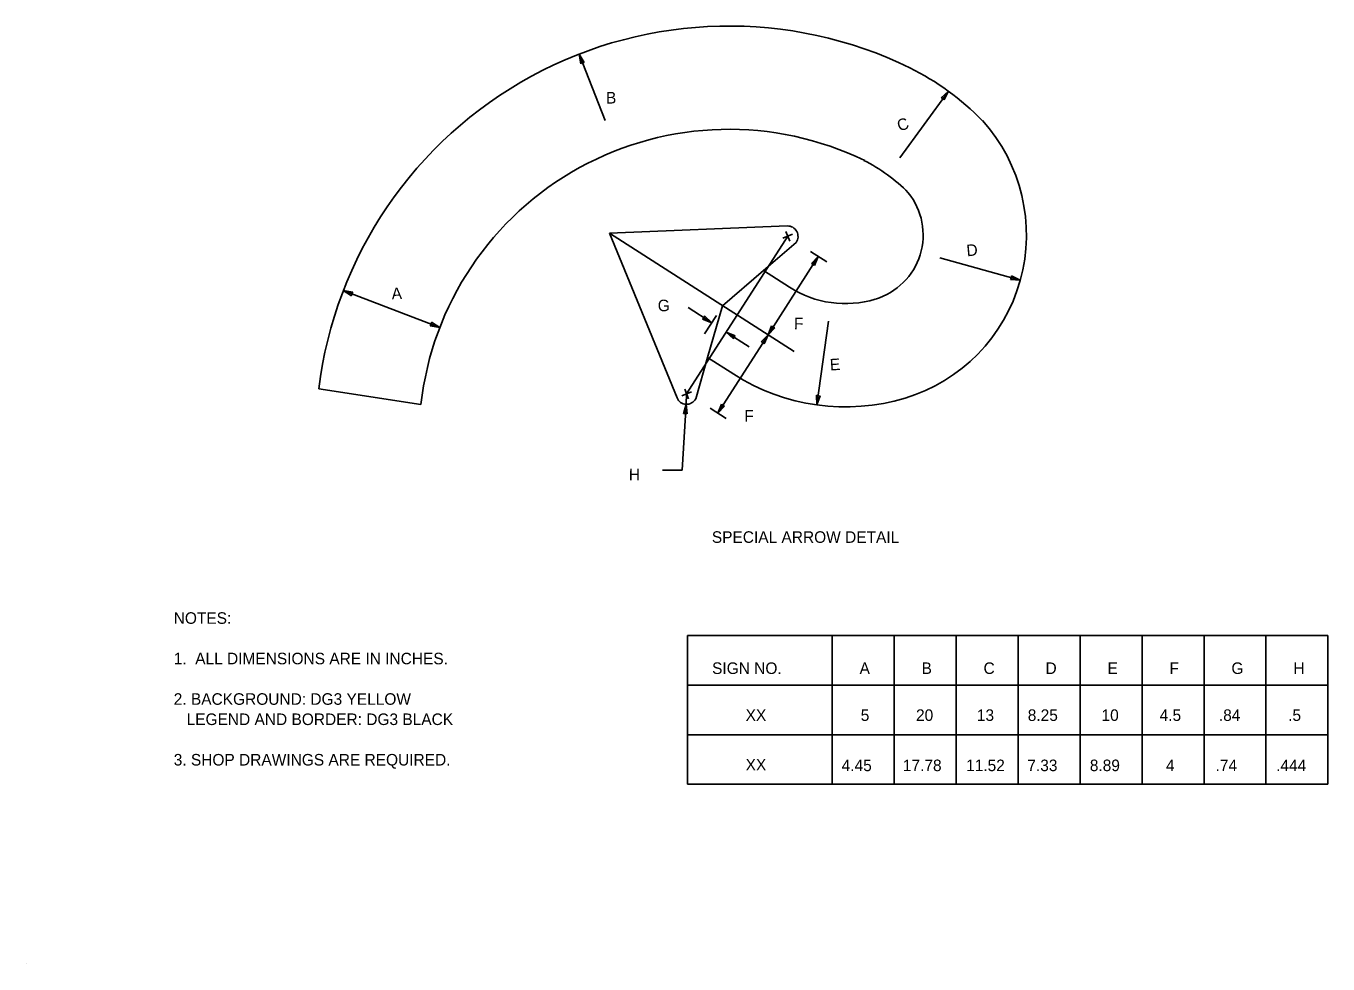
# Model space of a CAD drawing. Extents: x 582908 to 586040, y 1530940 to 1533040.
# Drawn here: x 582908 to 584484, y 1530940 to 1532075 of the extents above; entities that cross this region are included whole.
import ezdxf

# ---------------------------------------------------------------- set-up
doc = ezdxf.new("R2010")
doc.units = 0
for name, color, linetype in [('AdhocPoint_dp', 7, 'Continuous'), ('GSDims', 7, 'Continuous'), ('SignDetail', 7, 'Continuous'), ('TextLabel', 7, 'Continuous'), ('TextNotes', 7, 'Continuous'), ('TextTables', 7, 'Continuous')]:
    doc.layers.add(name, color=color, linetype=linetype)

msp = doc.modelspace()

# ---------------------------------------------------------------- linework, layer by layer
at = {"layer": 'AdhocPoint_dp'}
msp.add_line((582908.3, 1530939.8), (582908.3, 1530939.8), dxfattribs=at)
at = {"layer": 'GSDims'}
for p, q in [((583577.5, 1532040.8), (583609.1, 1531960.6)), ((583577.5, 1532040.8), (583579.7, 1532029.2)), ((583583.8, 1532030.8), (583577.5, 1532040.8)), ((583579.7, 1532029.2), (583581.4, 1532030.9)), ((583581.4, 1532030.9), (583583.8, 1532030.8)), ((583965.6, 1531915.4), (584024.4, 1531996.1)), ((584024.4, 1531996.1), (584015.8, 1531988)), ((584015.8, 1531988), (584018.1, 1531987.4)), ((584018.1, 1531987.4), (584019.3, 1531985.4)), ((584019.3, 1531985.4), (584024.4, 1531996.1)), ((583824.3, 1531818.1), (583835.9, 1531822.8)), ((583827.8, 1531826.2), (583832.4, 1531814.6)), ((583857.6, 1531801.8), (583877.2, 1531789.3)), ((583806.2, 1531701.1), (583866.9, 1531795.8)), ((583866.9, 1531795.8), (583858.8, 1531787.3)), ((583858.8, 1531787.3), (583861.1, 1531786.8)), ((583861.1, 1531786.8), (583862.5, 1531784.9)), ((583862.5, 1531784.9), (583866.9, 1531795.8)), ((584014.2, 1531794.2), (584111.4, 1531767.2)), ((584101, 1531770), (584099.6, 1531768.2)), ((584099.6, 1531768.2), (584111.4, 1531767.2)), ((584111.4, 1531767.2), (584100.8, 1531772.4)), ((584100.8, 1531772.4), (584101, 1531770)), ((583409, 1531710), (583292.2, 1531754.7)), ((583292.2, 1531754.7), (583302.3, 1531748.5)), ((583303.8, 1531752.6), (583292.2, 1531754.7)), ((583302.3, 1531750.9), (583303.8, 1531752.6)), ((583302.3, 1531748.5), (583302.3, 1531750.9)), ((583709.5, 1531734.2), (583738, 1531715.8)), ((583729, 1531721.6), (583727.1, 1531720.3)), ((583727.1, 1531720.3), (583738, 1531715.8)), ((583729.5, 1531724), (583729, 1531721.6)), ((583729.3, 1531702.2), (583743.7, 1531724.7)), ((583738, 1531715.8), (583729.5, 1531724)), ((583879.3, 1531717.5), (583865.3, 1531616.3)), ((583399, 1531713.9), (583397.4, 1531712.2)), ((583397.4, 1531712.2), (583409, 1531710)), ((583409, 1531710), (583398.9, 1531716.3)), ((583398.9, 1531716.3), (583399, 1531713.9)), ((583755.7, 1531704.5), (583783.2, 1531686.8)), ((583755.7, 1531704.5), (583764.3, 1531696.3)), ((583766.6, 1531700), (583755.7, 1531704.5)), ((583810.6, 1531712.1), (583806.2, 1531701.1)), ((583806.2, 1531701.1), (583814.3, 1531709.7)), ((583812, 1531710.1), (583810.6, 1531712.1)), ((583814.3, 1531709.7), (583812, 1531710.1)), ((583745.4, 1531606.4), (583806.2, 1531701.1)), ((583764.3, 1531696.3), (583764.7, 1531698.7)), ((583764.7, 1531698.7), (583766.6, 1531700)), ((583806.2, 1531701.1), (583798, 1531692.6)), ((583798, 1531692.6), (583800.4, 1531692.1)), ((583800.4, 1531692.1), (583801.7, 1531690.2)), ((583801.7, 1531690.2), (583806.2, 1531701.1)), ((583701.9, 1531627.3), (583713.5, 1531632)), ((583705.4, 1531635.4), (583710, 1531623.8)), ((583707.7, 1531629.6), (583707, 1531617.2)), ((583866.8, 1531626.9), (583864.7, 1531628.1)), ((583864.7, 1531628.1), (583865.3, 1531616.3)), ((583865.3, 1531616.3), (583869.1, 1531627.5)), ((583869.1, 1531627.5), (583866.8, 1531626.9)), ((583707, 1531617.2), (583702.4, 1531537.3)), ((583707, 1531617.2), (583704.1, 1531605.7)), ((583708.5, 1531605.5), (583707, 1531617.2)), ((583736.2, 1531612.4), (583755.7, 1531599.9)), ((583749.9, 1531617.4), (583745.4, 1531606.4)), ((583745.4, 1531606.4), (583753.6, 1531615)), ((583751.2, 1531615.5), (583749.9, 1531617.4)), ((583753.6, 1531615), (583751.2, 1531615.5)), ((583704.1, 1531605.7), (583706.4, 1531606.5)), ((583706.4, 1531606.5), (583708.5, 1531605.5)), ((583702.4, 1531537.3), (583678.6, 1531537.3))]:
    msp.add_line(p, q, dxfattribs=at)
at = {"layer": 'SignDetail'}
for p, q in [((583614.3, 1531824.2), (583829.4, 1531832.9)), ((583614.3, 1531824.2), (583837.7, 1531680.9)), ((583614.3, 1531824.2), (583696.1, 1531624.9)), ((583707.7, 1531629.6), (583830.1, 1531820.4)), ((583840.1, 1531813), (583800.6, 1531778.9)), ((583800.6, 1531778.9), (583751.2, 1531736.4)), ((583800.6, 1531778.9), (583832.2, 1531758.7)), ((583733.1, 1531673.7), (583751.2, 1531736.4)), ((583718.7, 1531623.6), (583733.1, 1531673.7)), ((583733.1, 1531673.7), (583764.7, 1531653.5)), ((583386.1, 1531616.8), (583262.5, 1531635.6))]:
    msp.add_line(p, q, dxfattribs=at)
for centre, radius, start, end in [((583758.8, 1531574.9), 500, 64.0026, 173.0199), ((583833.6, 1531734.2), 324, 44.3092, 63.5547), ((583912.6, 1531822.1), 206.3, 286.8096, 42.1395), ((583758.8, 1531574.9), 375, 64.0026, 173.5767), ((583833.6, 1531734.2), 198.9, 44.3092, 63.5547), ((583912.6, 1531822.1), 81.3, 286.8096, 38.803), ((583829.9, 1531820.3), 12.6, 324.4393, 92.3246), ((583899.7, 1531863.9), 125, 237.3246, 286.8677), ((583899.7, 1531863.9), 250, 237.3246, 286.8677), ((583707.7, 1531629.6), 12.5, 202.3246, 331.1534)]:
    msp.add_arc(centre, radius, start, end, dxfattribs=at)
at = {"layer": 'TextTables'}
for p, q in [((583708.8, 1531337.2), (583708.8, 1531157.2)), ((583708.8, 1531337.2), (584483.8, 1531337.2)), ((583883.8, 1531337.2), (583883.8, 1531157.2)), ((583958.8, 1531337.2), (583958.8, 1531157.2)), ((584033.8, 1531337.2), (584033.8, 1531157.2)), ((584108.8, 1531337.2), (584108.8, 1531157.2)), ((584183.8, 1531337.2), (584183.8, 1531157.2)), ((584258.8, 1531337.2), (584258.8, 1531157.2)), ((584333.8, 1531337.2), (584333.8, 1531157.2)), ((584408.8, 1531337.2), (584408.8, 1531157.2)), ((584483.8, 1531337.2), (584483.8, 1531157.2)), ((583708.8, 1531277.2), (584483.8, 1531277.2)), ((583708.8, 1531217.2), (584483.8, 1531217.2)), ((583708.8, 1531157.2), (584483.8, 1531157.2))]:
    msp.add_line(p, q, dxfattribs=at)

# ---------------------------------------------------------------- texts
at = {"layer": 'GSDims'}
for s, rotation, p in [('B', 359.8433, (583610.1, 1531981.1)), ('C', 20.0634, (583965.4, 1531947)), ('D', 5.3645, (584047, 1531796.1)), ('A', 2.778, (583351, 1531744)), ('G', 359.8433, (583672.7, 1531729.7)), ('F', 359.8433, (583837.5, 1531708)), ('E', 3.8579, (583881.5, 1531657.9)), ('F', 359.8433, (583777.4, 1531596.1)), ('H', 359.8433, (583637.8, 1531525.2))]:
    msp.add_text(s, height=14, rotation=rotation, dxfattribs=at).set_placement(p)
at = {"layer": 'TextLabel'}
msp.add_text('SPECIAL ARROW DETAIL', height=14, dxfattribs=at).set_placement((583738.2, 1531449.4))
at = {"layer": 'TextNotes'}
for s, p in [('NOTES:', (583087, 1531351.4)), ('1.  ALL DIMENSIONS ARE IN INCHES.', (583087, 1531302.4)), ('2. BACKGROUND: DG3 YELLOW ', (583087, 1531253.4)), ('   LEGEND AND BORDER: DG3 BLACK', (583087, 1531228.9)), ('3. SHOP DRAWINGS ARE REQUIRED.', (583087, 1531179.9))]:
    msp.add_text(s, height=14, dxfattribs=at).set_placement(p)
at = {"layer": 'TextTables'}
for s, p in [('SIGN NO.', (583738.5, 1531290.7)), ('A', (583917, 1531290.7)), ('B', (583992, 1531290.7)), ('C', (584067, 1531290.7)), ('D', (584142, 1531290.7)), ('E', (584217, 1531290.7)), ('F', (584292, 1531290.7)), ('G', (584367, 1531290.7)), ('H', (584442, 1531290.7)), ('XX', (583779.1, 1531233.9)), ('5', (583918.4, 1531233.9)), ('20', (583985.3, 1531233.9)), ('13', (584058.9, 1531233.9)), ('8.25', (584120.5, 1531233.9)), ('10', (584209.8, 1531233.9)), ('4.5', (584280.1, 1531233.9)), ('.84', (584351.8, 1531233.9)), ('.5', (584435.6, 1531233.9)), ('XX', (583779.1, 1531173.9)), ('4.45', (583895.3, 1531173.1)), ('17.78', (583969.4, 1531173.1)), ('11.52', (584045.9, 1531173.1)), ('7.33', (584120, 1531173.1)), ('8.89', (584195.6, 1531173.1)), ('4', (584287.8, 1531173.1)), ('.74', (584347.8, 1531173.1)), ('.444', (584421.1, 1531173.1))]:
    msp.add_text(s, height=14, dxfattribs=at).set_placement(p)

doc.saveas('drawing.dxf')
